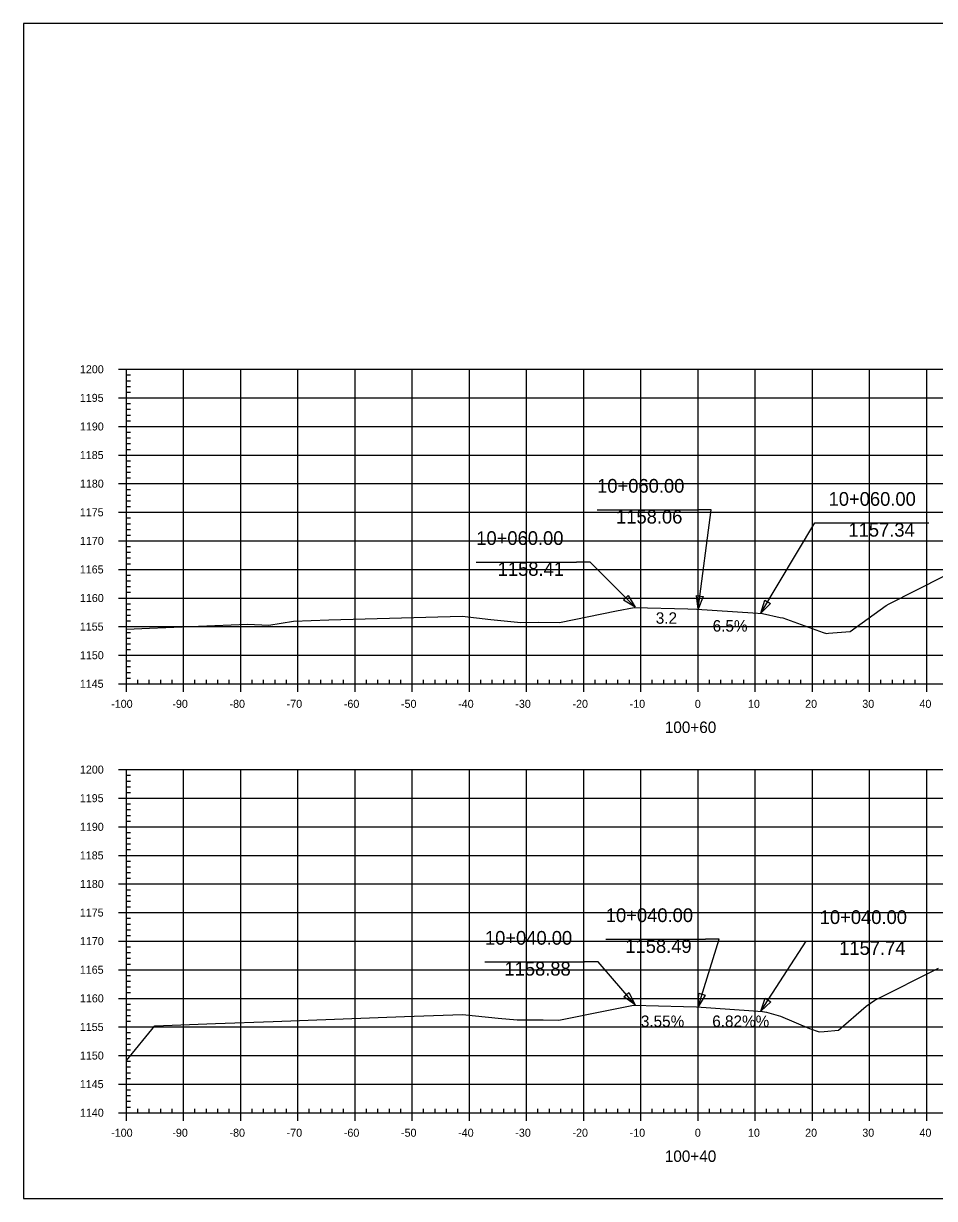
# Model space of a CAD drawing. Extents: x 688474 to 694748, y 765018 to 767373.
# Drawn here: x 689619.8 to 689779.2, y 765303.6 to 765509.1 of the extents above; entities that cross this region are included whole.
import ezdxf

# ---------------------------------------------------------------- set-up
doc = ezdxf.new("R2010")
doc.units = 0
for name, color, linetype in [('60', 7, 'Continuous'), ('Default', 7, 'Continuous'), ('R_Exist Surface', 7, 'Continuous'), ('R_Grid', 7, 'Continuous'), ('R_No Plot', 7, 'Continuous'), ('R_Xsect Slope', 7, 'Continuous')]:
    doc.layers.add(name, color=color, linetype=linetype)

msp = doc.modelspace()

# ---------------------------------------------------------------- linework, layer by layer
at = {"layer": '60'}
for p, q in [((689636.42, 765448.6), (689639.22, 765448.6)), ((689637.82, 765393.6), (689637.82, 765448.6)), ((689637.82, 765447.6), (689638.52, 765447.6)), ((689637.82, 765446.6), (689638.52, 765446.6)), ((689637.82, 765445.6), (689638.52, 765445.6)), ((689636.42, 765443.6), (689639.22, 765443.6)), ((689637.82, 765444.6), (689638.52, 765444.6)), ((689637.82, 765442.6), (689638.52, 765442.6)), ((689637.82, 765441.6), (689638.52, 765441.6)), ((689637.82, 765440.6), (689638.52, 765440.6)), ((689637.82, 765439.6), (689638.52, 765439.6)), ((689636.42, 765438.6), (689639.22, 765438.6)), ((689637.82, 765437.6), (689638.52, 765437.6)), ((689637.82, 765436.6), (689638.52, 765436.6)), ((689637.82, 765435.6), (689638.52, 765435.6)), ((689636.42, 765433.6), (689639.22, 765433.6)), ((689637.82, 765434.6), (689638.52, 765434.6)), ((689637.82, 765432.6), (689638.52, 765432.6)), ((689637.82, 765431.6), (689638.52, 765431.6)), ((689637.82, 765430.6), (689638.52, 765430.6)), ((689637.82, 765429.6), (689638.52, 765429.6)), ((689636.42, 765428.6), (689639.22, 765428.6)), ((689637.82, 765427.6), (689638.52, 765427.6)), ((689637.82, 765426.6), (689638.52, 765426.6)), ((689637.82, 765425.6), (689638.52, 765425.6)), ((689636.42, 765423.6), (689639.22, 765423.6)), ((689637.82, 765424.6), (689638.52, 765424.6)), ((689637.82, 765422.6), (689638.52, 765422.6)), ((689637.82, 765421.6), (689638.52, 765421.6)), ((689637.82, 765420.6), (689638.52, 765420.6)), ((689637.82, 765419.6), (689638.52, 765419.6)), ((689636.42, 765418.6), (689639.22, 765418.6)), ((689637.82, 765417.6), (689638.52, 765417.6)), ((689637.82, 765416.6), (689638.52, 765416.6)), ((689637.82, 765415.6), (689638.52, 765415.6)), ((689637.82, 765414.6), (689638.52, 765414.6)), ((689636.42, 765413.6), (689639.22, 765413.6)), ((689637.82, 765412.6), (689638.52, 765412.6)), ((689637.82, 765411.6), (689638.52, 765411.6)), ((689637.82, 765410.6), (689638.52, 765410.6)), ((689636.42, 765408.6), (689639.22, 765408.6)), ((689637.82, 765409.6), (689638.52, 765409.6)), ((689637.82, 765407.6), (689638.52, 765407.6)), ((689637.82, 765406.6), (689638.52, 765406.6)), ((689637.82, 765405.6), (689638.52, 765405.6)), ((689637.82, 765404.6), (689638.52, 765404.6)), ((689636.42, 765403.6), (689639.22, 765403.6)), ((689637.82, 765402.6), (689638.52, 765402.6)), ((689637.82, 765401.6), (689638.52, 765401.6)), ((689637.82, 765400.6), (689638.52, 765400.6)), ((689636.42, 765398.6), (689639.22, 765398.6)), ((689637.82, 765399.6), (689638.52, 765399.6)), ((689637.82, 765397.6), (689638.52, 765397.6)), ((689637.82, 765396.6), (689638.52, 765396.6)), ((689637.82, 765395.6), (689638.52, 765395.6)), ((689637.82, 765392.2), (689637.82, 765395)), ((689637.82, 765394.6), (689638.52, 765394.6)), ((689639.82, 765393.6), (689639.82, 765394.3)), ((689641.82, 765393.6), (689641.82, 765394.3)), ((689643.82, 765393.6), (689643.82, 765394.3)), ((689645.82, 765393.6), (689645.82, 765394.3)), ((689647.82, 765392.2), (689647.82, 765395)), ((689649.82, 765393.6), (689649.82, 765394.3)), ((689651.82, 765393.6), (689651.82, 765394.3)), ((689653.82, 765393.6), (689653.82, 765394.3)), ((689655.82, 765393.6), (689655.82, 765394.3)), ((689657.82, 765392.2), (689657.82, 765395)), ((689659.82, 765393.6), (689659.82, 765394.3)), ((689661.82, 765393.6), (689661.82, 765394.3)), ((689663.82, 765393.6), (689663.82, 765394.3)), ((689665.82, 765393.6), (689665.82, 765394.3)), ((689667.82, 765392.2), (689667.82, 765395)), ((689669.82, 765393.6), (689669.82, 765394.3)), ((689671.82, 765393.6), (689671.82, 765394.3)), ((689673.82, 765393.6), (689673.82, 765394.3)), ((689675.82, 765393.6), (689675.82, 765394.3)), ((689677.82, 765392.2), (689677.82, 765395)), ((689679.82, 765393.6), (689679.82, 765394.3)), ((689681.82, 765393.6), (689681.82, 765394.3)), ((689683.82, 765393.6), (689683.82, 765394.3)), ((689685.82, 765393.6), (689685.82, 765394.3)), ((689687.82, 765392.2), (689687.82, 765395)), ((689689.82, 765393.6), (689689.82, 765394.3)), ((689691.82, 765393.6), (689691.82, 765394.3)), ((689693.82, 765393.6), (689693.82, 765394.3)), ((689695.82, 765393.6), (689695.82, 765394.3)), ((689697.82, 765392.2), (689697.82, 765395)), ((689699.82, 765393.6), (689699.82, 765394.3)), ((689701.82, 765393.6), (689701.82, 765394.3)), ((689703.82, 765393.6), (689703.82, 765394.3)), ((689705.82, 765393.6), (689705.82, 765394.3)), ((689707.82, 765392.2), (689707.82, 765395)), ((689709.82, 765393.6), (689709.82, 765394.3)), ((689711.82, 765393.6), (689711.82, 765394.3)), ((689713.82, 765393.6), (689713.82, 765394.3)), ((689715.82, 765393.6), (689715.82, 765394.3)), ((689717.82, 765392.2), (689717.82, 765395)), ((689719.82, 765393.6), (689719.82, 765394.3)), ((689721.82, 765393.6), (689721.82, 765394.3)), ((689723.82, 765393.6), (689723.82, 765394.3)), ((689725.82, 765393.6), (689725.82, 765394.3)), ((689727.82, 765392.2), (689727.82, 765395)), ((689729.82, 765393.6), (689729.82, 765394.3)), ((689731.82, 765393.6), (689731.82, 765394.3)), ((689733.82, 765393.6), (689733.82, 765394.3)), ((689735.82, 765393.6), (689735.82, 765394.3)), ((689737.82, 765392.2), (689737.82, 765395)), ((689739.82, 765393.6), (689739.82, 765394.3)), ((689741.82, 765393.6), (689741.82, 765394.3)), ((689743.82, 765393.6), (689743.82, 765394.3)), ((689745.82, 765393.6), (689745.82, 765394.3)), ((689747.82, 765392.2), (689747.82, 765395)), ((689749.82, 765393.6), (689749.82, 765394.3)), ((689751.82, 765393.6), (689751.82, 765394.3)), ((689753.82, 765393.6), (689753.82, 765394.3)), ((689755.82, 765393.6), (689755.82, 765394.3)), ((689757.82, 765392.2), (689757.82, 765395)), ((689759.82, 765393.6), (689759.82, 765394.3)), ((689761.82, 765393.6), (689761.82, 765394.3)), ((689763.82, 765393.6), (689763.82, 765394.3)), ((689765.82, 765393.6), (689765.82, 765394.3)), ((689767.82, 765392.2), (689767.82, 765395)), ((689769.82, 765393.6), (689769.82, 765394.3)), ((689771.82, 765393.6), (689771.82, 765394.3)), ((689773.82, 765393.6), (689773.82, 765394.3)), ((689775.82, 765393.6), (689775.82, 765394.3)), ((689777.82, 765392.2), (689777.82, 765395)), ((689636.42, 765393.6), (689639.22, 765393.6)), ((689637.82, 765393.6), (689837.82, 765393.6)), ((689636.42, 765378.6), (689639.22, 765378.6)), ((689637.82, 765318.6), (689637.82, 765378.6)), ((689637.82, 765377.6), (689638.52, 765377.6)), ((689637.82, 765376.6), (689638.52, 765376.6)), ((689637.82, 765375.6), (689638.52, 765375.6)), ((689636.42, 765373.6), (689639.22, 765373.6)), ((689637.82, 765374.6), (689638.52, 765374.6)), ((689637.82, 765372.6), (689638.52, 765372.6)), ((689637.82, 765371.6), (689638.52, 765371.6)), ((689637.82, 765370.6), (689638.52, 765370.6)), ((689637.82, 765369.6), (689638.52, 765369.6)), ((689636.42, 765368.6), (689639.22, 765368.6)), ((689637.82, 765367.6), (689638.52, 765367.6)), ((689637.82, 765366.6), (689638.52, 765366.6)), ((689637.82, 765365.6), (689638.52, 765365.6)), ((689636.42, 765363.6), (689639.22, 765363.6)), ((689637.82, 765364.6), (689638.52, 765364.6)), ((689637.82, 765362.6), (689638.52, 765362.6)), ((689637.82, 765361.6), (689638.52, 765361.6)), ((689637.82, 765360.6), (689638.52, 765360.6)), ((689637.82, 765359.6), (689638.52, 765359.6)), ((689636.42, 765358.6), (689639.22, 765358.6)), ((689637.82, 765357.6), (689638.52, 765357.6)), ((689637.82, 765356.6), (689638.52, 765356.6)), ((689637.82, 765355.6), (689638.52, 765355.6)), ((689636.42, 765353.6), (689639.22, 765353.6)), ((689637.82, 765354.6), (689638.52, 765354.6)), ((689637.82, 765352.6), (689638.52, 765352.6)), ((689637.82, 765351.6), (689638.52, 765351.6)), ((689637.82, 765350.6), (689638.52, 765350.6)), ((689637.82, 765349.6), (689638.52, 765349.6)), ((689636.42, 765348.6), (689639.22, 765348.6)), ((689637.82, 765347.6), (689638.52, 765347.6)), ((689637.82, 765346.6), (689638.52, 765346.6)), ((689637.82, 765345.6), (689638.52, 765345.6)), ((689636.42, 765343.6), (689639.22, 765343.6)), ((689637.82, 765344.6), (689638.52, 765344.6)), ((689637.82, 765342.6), (689638.52, 765342.6)), ((689637.82, 765341.6), (689638.52, 765341.6)), ((689637.82, 765340.6), (689638.52, 765340.6)), ((689636.42, 765338.6), (689639.22, 765338.6)), ((689637.82, 765339.6), (689638.52, 765339.6)), ((689637.82, 765337.6), (689638.52, 765337.6)), ((689637.82, 765336.6), (689638.52, 765336.6)), ((689637.82, 765335.6), (689638.52, 765335.6)), ((689637.82, 765334.6), (689638.52, 765334.6)), ((689636.42, 765333.6), (689639.22, 765333.6)), ((689637.82, 765332.6), (689638.52, 765332.6)), ((689637.82, 765331.6), (689638.52, 765331.6)), ((689637.82, 765330.6), (689638.52, 765330.6)), ((689636.42, 765328.6), (689639.22, 765328.6)), ((689637.82, 765329.6), (689638.52, 765329.6)), ((689637.82, 765327.6), (689638.52, 765327.6)), ((689637.82, 765326.6), (689638.52, 765326.6)), ((689637.82, 765325.6), (689638.52, 765325.6)), ((689637.82, 765324.6), (689638.52, 765324.6)), ((689636.42, 765323.6), (689639.22, 765323.6)), ((689637.82, 765322.6), (689638.52, 765322.6)), ((689637.82, 765321.6), (689638.52, 765321.6)), ((689637.82, 765320.6), (689638.52, 765320.6)), ((689636.42, 765318.6), (689639.22, 765318.6)), ((689637.82, 765317.2), (689637.82, 765320)), ((689637.82, 765319.6), (689638.52, 765319.6)), ((689637.82, 765318.6), (689837.82, 765318.6)), ((689639.82, 765318.6), (689639.82, 765319.3)), ((689641.82, 765318.6), (689641.82, 765319.3)), ((689643.82, 765318.6), (689643.82, 765319.3)), ((689645.82, 765318.6), (689645.82, 765319.3)), ((689647.82, 765317.2), (689647.82, 765320)), ((689649.82, 765318.6), (689649.82, 765319.3)), ((689651.82, 765318.6), (689651.82, 765319.3)), ((689653.82, 765318.6), (689653.82, 765319.3)), ((689655.82, 765318.6), (689655.82, 765319.3)), ((689657.82, 765317.2), (689657.82, 765320)), ((689659.82, 765318.6), (689659.82, 765319.3)), ((689661.82, 765318.6), (689661.82, 765319.3)), ((689663.82, 765318.6), (689663.82, 765319.3)), ((689665.82, 765318.6), (689665.82, 765319.3)), ((689667.82, 765317.2), (689667.82, 765320)), ((689669.82, 765318.6), (689669.82, 765319.3)), ((689671.82, 765318.6), (689671.82, 765319.3)), ((689673.82, 765318.6), (689673.82, 765319.3)), ((689675.82, 765318.6), (689675.82, 765319.3)), ((689677.82, 765317.2), (689677.82, 765320)), ((689679.82, 765318.6), (689679.82, 765319.3)), ((689681.82, 765318.6), (689681.82, 765319.3)), ((689683.82, 765318.6), (689683.82, 765319.3)), ((689685.82, 765318.6), (689685.82, 765319.3)), ((689687.82, 765317.2), (689687.82, 765320)), ((689689.82, 765318.6), (689689.82, 765319.3)), ((689691.82, 765318.6), (689691.82, 765319.3)), ((689693.82, 765318.6), (689693.82, 765319.3)), ((689695.82, 765318.6), (689695.82, 765319.3)), ((689697.82, 765317.2), (689697.82, 765320)), ((689699.82, 765318.6), (689699.82, 765319.3)), ((689701.82, 765318.6), (689701.82, 765319.3)), ((689703.82, 765318.6), (689703.82, 765319.3)), ((689705.82, 765318.6), (689705.82, 765319.3)), ((689707.82, 765317.2), (689707.82, 765320)), ((689709.82, 765318.6), (689709.82, 765319.3)), ((689711.82, 765318.6), (689711.82, 765319.3)), ((689713.82, 765318.6), (689713.82, 765319.3)), ((689715.82, 765318.6), (689715.82, 765319.3)), ((689717.82, 765317.2), (689717.82, 765320)), ((689719.82, 765318.6), (689719.82, 765319.3)), ((689721.82, 765318.6), (689721.82, 765319.3)), ((689723.82, 765318.6), (689723.82, 765319.3)), ((689725.82, 765318.6), (689725.82, 765319.3)), ((689727.82, 765317.2), (689727.82, 765320)), ((689729.82, 765318.6), (689729.82, 765319.3)), ((689731.82, 765318.6), (689731.82, 765319.3)), ((689733.82, 765318.6), (689733.82, 765319.3)), ((689735.82, 765318.6), (689735.82, 765319.3)), ((689737.82, 765317.2), (689737.82, 765320)), ((689739.82, 765318.6), (689739.82, 765319.3)), ((689741.82, 765318.6), (689741.82, 765319.3)), ((689743.82, 765318.6), (689743.82, 765319.3)), ((689745.82, 765318.6), (689745.82, 765319.3)), ((689747.82, 765317.2), (689747.82, 765320)), ((689749.82, 765318.6), (689749.82, 765319.3)), ((689751.82, 765318.6), (689751.82, 765319.3)), ((689753.82, 765318.6), (689753.82, 765319.3)), ((689755.82, 765318.6), (689755.82, 765319.3)), ((689757.82, 765317.2), (689757.82, 765320)), ((689759.82, 765318.6), (689759.82, 765319.3)), ((689761.82, 765318.6), (689761.82, 765319.3)), ((689763.82, 765318.6), (689763.82, 765319.3)), ((689765.82, 765318.6), (689765.82, 765319.3)), ((689767.82, 765317.2), (689767.82, 765320)), ((689769.82, 765318.6), (689769.82, 765319.3)), ((689771.82, 765318.6), (689771.82, 765319.3)), ((689773.82, 765318.6), (689773.82, 765319.3)), ((689775.82, 765318.6), (689775.82, 765319.3)), ((689777.82, 765317.2), (689777.82, 765320))]:
    msp.add_line(p, q, dxfattribs=at)
at = {"layer": 'R_Exist Surface'}
for p, q in [((689720.17, 765424.02), (689737.7, 765424.02)), ((689760.66, 765421.73), (689778.18, 765421.73)), ((689699.02, 765414.88), (689716.55, 765414.88)), ((689721.69, 765348.94), (689739.11, 765348.94)), ((689759.11, 765348.6), (689776.52, 765348.6)), ((689700.54, 765344.98), (689717.95, 765344.98))]:
    msp.add_line(p, q, dxfattribs=at)
for points in [[(689737.82, 765406.66), (689740.1, 765424.02), (689737.7, 765424.02)], [(689748.82, 765405.94), (689758.26, 765421.73), (689760.66, 765421.73)], [(689637.82, 765403.16), (689641.89, 765403.34), (689658.99, 765404.04), (689662.73, 765403.86), (689667.04, 765404.58), (689673.23, 765404.8), (689696.54, 765405.42), (689701.58, 765404.86), (689706.85, 765404.33), (689709.94, 765404.35), (689713.57, 765404.32), (689723.58, 765406.36), (689726.62, 765406.97), (689736.01, 765406.72), (689737.59, 765406.68), (689747.42, 765406.03), (689749.09, 765405.92), (689752.18, 765405.21), (689752.65, 765405.11), (689759.73, 765402.59), (689760.3, 765402.41), (689760.63, 765402.44), (689764.46, 765402.75), (689770.71, 765407.28), (689771.23, 765407.6), (689785.66, 765414.85)], [(689726.82, 765407.01), (689718.95, 765414.88), (689716.55, 765414.88)], [(689737.82, 765337.09), (689741.51, 765348.94), (689739.11, 765348.94)], [(689748.82, 765336.34), (689756.71, 765348.6), (689759.11, 765348.6)], [(689726.82, 765337.48), (689720.35, 765344.98), (689717.95, 765344.98)], [(689637.82, 765327.75), (689642.8, 765333.79), (689653.43, 765334.21), (689663.51, 765334.57), (689686.45, 765335.41), (689696.6, 765335.78), (689702.88, 765335.15), (689706.16, 765334.86), (689710.73, 765334.82), (689713.48, 765334.77), (689721.84, 765336.47), (689726.52, 765337.42), (689735.25, 765337.17), (689737.55, 765337.11), (689746.72, 765336.48), (689749.07, 765336.32), (689749.78, 765336.16), (689752.25, 765335.47), (689757.31, 765333.33), (689759, 765332.72), (689759.89, 765332.79), (689762.4, 765333.03), (689767.23, 765337.22), (689768.73, 765338.31), (689779.88, 765343.87)]]:
    msp.add_lwpolyline(points, dxfattribs=at)
for points in [[(689726.82, 765407.01), (689724.76, 765408.25), (689725.58, 765409.07)], [(689737.82, 765406.66), (689737.54, 765409.05), (689738.7, 765408.89)], [(689748.82, 765405.94), (689749.51, 765408.24), (689750.51, 765407.64)], [(689726.82, 765337.48), (689724.86, 765338.87), (689725.74, 765339.63)], [(689737.82, 765337.09), (689737.95, 765339.49), (689739.07, 765339.14)], [(689748.82, 765336.34), (689749.59, 765338.61), (689750.57, 765337.98)]]:
    msp.add_lwpolyline(points, close=True, dxfattribs=at)
at = {"layer": 'R_Grid'}
for p, q in [((689637.82, 765448.6), (689837.82, 765448.6)), ((689637.82, 765393.6), (689637.82, 765448.6)), ((689647.82, 765393.6), (689647.82, 765448.6)), ((689657.82, 765393.6), (689657.82, 765448.6)), ((689667.82, 765393.6), (689667.82, 765448.6)), ((689677.82, 765393.6), (689677.82, 765448.6)), ((689687.82, 765393.6), (689687.82, 765448.6)), ((689697.82, 765393.6), (689697.82, 765448.6)), ((689707.82, 765393.6), (689707.82, 765448.6)), ((689717.82, 765393.6), (689717.82, 765448.6)), ((689727.82, 765393.6), (689727.82, 765448.6)), ((689737.82, 765393.6), (689737.82, 765448.6)), ((689747.82, 765393.6), (689747.82, 765448.6)), ((689757.82, 765393.6), (689757.82, 765448.6)), ((689767.82, 765393.6), (689767.82, 765448.6)), ((689777.82, 765393.6), (689777.82, 765448.6)), ((689637.82, 765443.6), (689837.82, 765443.6)), ((689637.82, 765438.6), (689837.82, 765438.6)), ((689637.82, 765433.6), (689837.82, 765433.6)), ((689637.82, 765428.6), (689837.82, 765428.6)), ((689637.82, 765423.6), (689837.82, 765423.6)), ((689637.82, 765418.6), (689837.82, 765418.6)), ((689637.82, 765413.6), (689837.82, 765413.6)), ((689637.82, 765408.6), (689837.82, 765408.6)), ((689637.82, 765403.6), (689837.82, 765403.6)), ((689637.82, 765398.6), (689837.82, 765398.6)), ((689637.82, 765393.6), (689837.82, 765393.6)), ((689637.82, 765378.6), (689837.82, 765378.6)), ((689637.82, 765318.6), (689637.82, 765378.6)), ((689647.82, 765318.6), (689647.82, 765378.6)), ((689657.82, 765318.6), (689657.82, 765378.6)), ((689667.82, 765318.6), (689667.82, 765378.6)), ((689677.82, 765318.6), (689677.82, 765378.6)), ((689687.82, 765318.6), (689687.82, 765378.6)), ((689697.82, 765318.6), (689697.82, 765378.6)), ((689707.82, 765318.6), (689707.82, 765378.6)), ((689717.82, 765318.6), (689717.82, 765378.6)), ((689727.82, 765318.6), (689727.82, 765378.6)), ((689737.82, 765318.6), (689737.82, 765378.6)), ((689747.82, 765318.6), (689747.82, 765378.6)), ((689757.82, 765318.6), (689757.82, 765378.6)), ((689767.82, 765318.6), (689767.82, 765378.6)), ((689777.82, 765318.6), (689777.82, 765378.6)), ((689637.82, 765373.6), (689837.82, 765373.6)), ((689637.82, 765368.6), (689837.82, 765368.6)), ((689637.82, 765363.6), (689837.82, 765363.6)), ((689637.82, 765358.6), (689837.82, 765358.6)), ((689637.82, 765353.6), (689837.82, 765353.6)), ((689637.82, 765348.6), (689837.82, 765348.6)), ((689637.82, 765343.6), (689837.82, 765343.6)), ((689637.82, 765338.6), (689837.82, 765338.6)), ((689637.82, 765333.6), (689837.82, 765333.6)), ((689637.82, 765328.6), (689837.82, 765328.6)), ((689637.82, 765323.6), (689837.82, 765323.6)), ((689637.82, 765318.6), (689837.82, 765318.6))]:
    msp.add_line(p, q, dxfattribs=at)
at = {"layer": 'R_No Plot'}
msp.add_lwpolyline([(689619.82, 765303.6), (689936, 765303.6), (689936, 765509.06), (689619.82, 765509.06)], close=True, dxfattribs=at)

# ---------------------------------------------------------------- texts
at = {"layer": '60'}
for s, height, p in [('1200', 1.4, (689629.69, 765447.9)), ('1195', 1.4, (689629.67, 765442.9)), ('1190', 1.4, (689629.69, 765437.9)), ('1185', 1.4, (689629.67, 765432.9)), ('1180', 1.4, (689629.69, 765427.9)), ('1175', 1.4, (689629.67, 765422.9)), ('1170', 1.4, (689629.69, 765417.9)), ('1165', 1.4, (689629.67, 765412.9)), ('1160', 1.4, (689629.69, 765407.9)), ('1155', 1.4, (689629.67, 765402.9)), ('1150', 1.4, (689629.69, 765397.9)), ('1145', 1.4, (689629.67, 765392.9)), ('-100', 1.4, (689635.16, 765389.4)), ('-90', 1.4, (689645.86, 765389.4)), ('-80', 1.4, (689655.86, 765389.4)), ('-70', 1.4, (689665.86, 765389.4)), ('-60', 1.4, (689675.86, 765389.4)), ('-50', 1.4, (689685.86, 765389.4)), ('-40', 1.4, (689695.86, 765389.4)), ('-30', 1.4, (689705.86, 765389.4)), ('-20', 1.4, (689715.86, 765389.4)), ('-10', 1.4, (689725.86, 765389.4)), ('0', 1.4, (689737.26, 765389.4)), ('10', 1.4, (689746.56, 765389.4)), ('20', 1.4, (689756.56, 765389.4)), ('30', 1.4, (689766.56, 765389.4)), ('40', 1.4, (689776.56, 765389.4)), ('100+60', 2, (689732.01, 765385)), ('1200', 1.4, (689629.69, 765377.9)), ('1195', 1.4, (689629.67, 765372.9)), ('1190', 1.4, (689629.69, 765367.9)), ('1185', 1.4, (689629.67, 765362.9)), ('1180', 1.4, (689629.69, 765357.9)), ('1175', 1.4, (689629.67, 765352.9)), ('1170', 1.4, (689629.69, 765347.9)), ('1165', 1.4, (689629.67, 765342.9)), ('1160', 1.4, (689629.69, 765337.9)), ('1155', 1.4, (689629.67, 765332.9)), ('1150', 1.4, (689629.69, 765327.9)), ('1145', 1.4, (689629.67, 765322.9)), ('1140', 1.4, (689629.69, 765317.9)), ('-100', 1.4, (689635.16, 765314.4)), ('-90', 1.4, (689645.86, 765314.4)), ('-80', 1.4, (689655.86, 765314.4)), ('-70', 1.4, (689665.86, 765314.4)), ('-60', 1.4, (689675.86, 765314.4)), ('-50', 1.4, (689685.86, 765314.4)), ('-40', 1.4, (689695.86, 765314.4)), ('-30', 1.4, (689705.86, 765314.4)), ('-20', 1.4, (689715.86, 765314.4)), ('-10', 1.4, (689725.86, 765314.4)), ('0', 1.4, (689737.26, 765314.4)), ('10', 1.4, (689746.56, 765314.4)), ('20', 1.4, (689756.56, 765314.4)), ('30', 1.4, (689766.56, 765314.4)), ('40', 1.4, (689776.56, 765314.4)), ('100+40', 2, (689732.01, 765310))]:
    msp.add_text(s, height=height, dxfattribs=at).set_placement(p)
at = {"layer": 'Default'}
for s, p in [('3.2', (689730.43, 765404.1)), ('6.5%', (689740.38, 765402.73)), ('3.55%', (689727.82, 765333.6)), ('6.82%%', (689740.31, 765333.6))]:
    msp.add_text(s, height=2, dxfattribs=at).set_placement(p)
at = {"layer": 'R_Xsect Slope'}
for s, p in [('10+060.00', (689720.17, 765427.02)), ('10+060.00', (689760.66, 765424.73)), ('1158.06', (689723.48, 765421.62)), ('1157.34', (689764.13, 765419.33)), ('10+060.00', (689699.02, 765417.88)), ('1158.41', (689702.77, 765412.48)), ('10+040.00', (689721.69, 765351.94)), ('10+040.00', (689759.11, 765351.6)), ('10+040.00', (689700.54, 765347.98)), ('1158.49', (689725.1, 765346.54)), ('1157.74', (689762.52, 765346.2)), ('1158.88', (689703.95, 765342.58))]:
    msp.add_text(s, height=2.4, dxfattribs=at).set_placement(p)

doc.saveas('drawing.dxf')
